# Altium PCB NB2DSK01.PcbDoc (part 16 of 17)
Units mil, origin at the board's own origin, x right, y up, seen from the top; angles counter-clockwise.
Board outline 11815 x 6500.03 mil, 8 copper layers (Top Layer, MidLayer1, MidLayer2, GND, PWR, MidLayer3, MidLayer4, Bottom Layer), stack 74.62 mil thick; 798 components, 1002 nets, 3927 pads, 3182 vias.
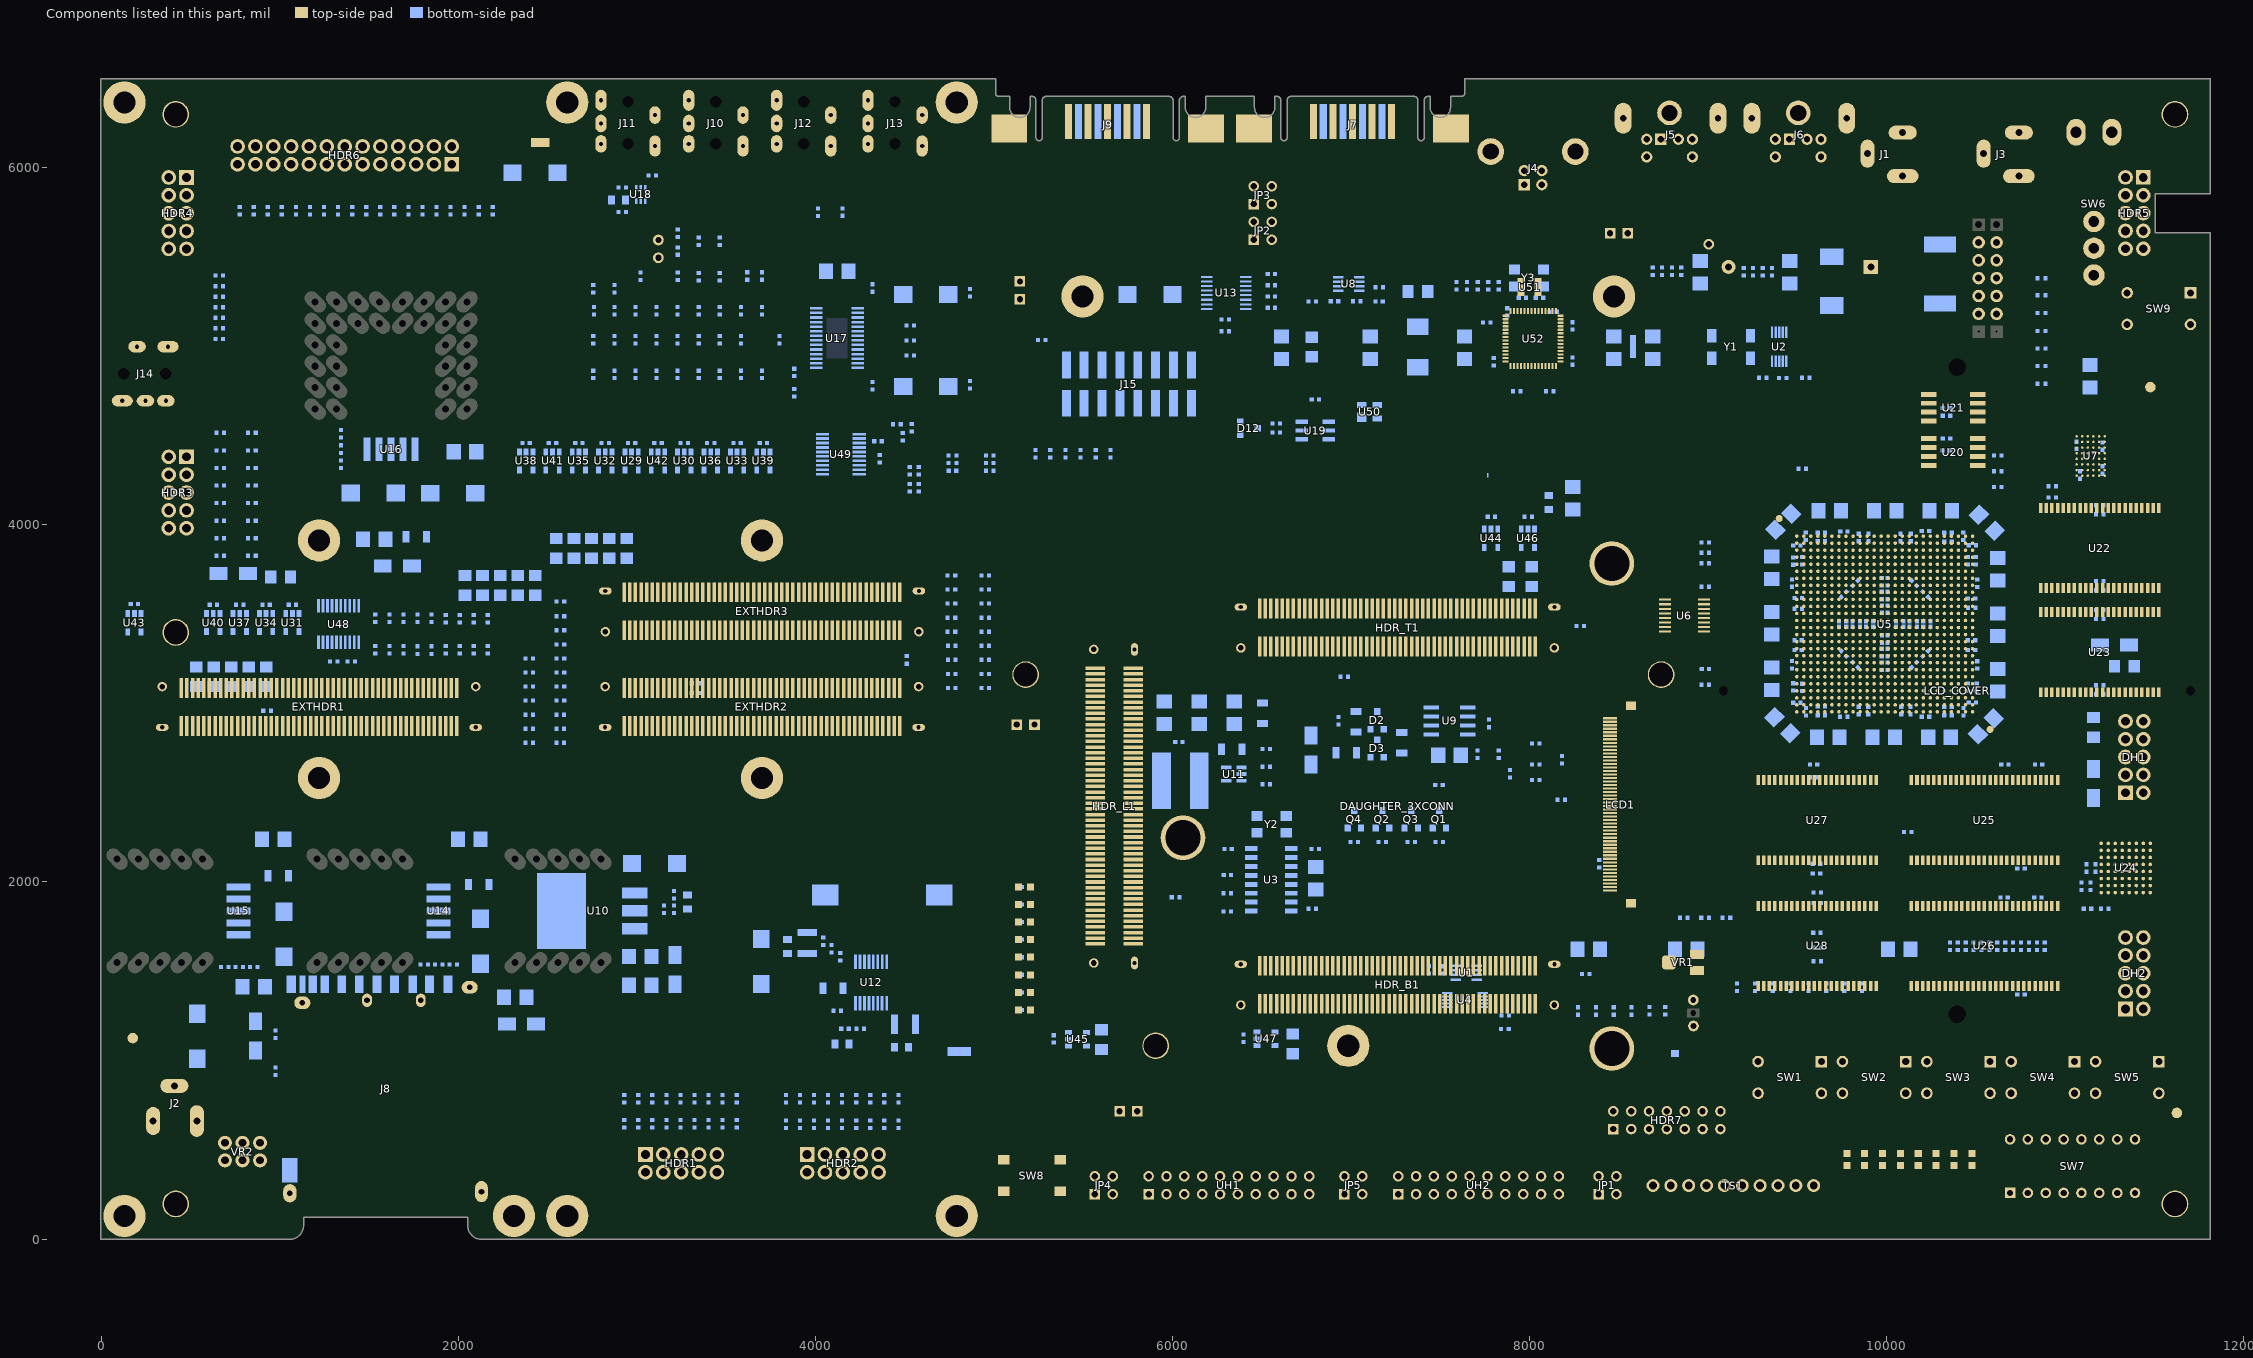
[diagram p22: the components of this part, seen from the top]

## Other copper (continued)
MidLayer3:
  region: 8912,4978.5 8912,4925.5 8926,4925.5 8926,4978.5
  rectangle net 1V2: 9204,3297 9401,3519
  rectangle net CSGND: 4303,4235 4344,4287.4
  rectangle net CSGND: 4284,4383 4346,4524
  rectangle net CSGND: 4344,4235 4519,4524
  rectangle net CSGND: 3997,4235 4303,4524
  rectangle net CSGND: 1196,3228 1468,3588
  rectangle net SHIELD: 10091,89 10495,228
  region net GND: 970.8,5426.84 970.8,4556 2281.17,4556 2281.17,5426.84
  rectangle net AUGND: 3966,4688.98 4276.87,4842.65
  rectangle net 1V2: 9295.68,3398.45 9533.68,3492.45
  rectangle net VCCX: 2228,1458 2873.68,2208
  rectangle net GND: 17,1458 643.68,2208
  rectangle net GND: 1118,1458 1763.68,2208
  text "L3" at 8850.5,4934.5 h35
Bottom Layer:
  rectangle net CAN_V+: 6801.84,6233 6886.4,6379
  rectangle: 6911.09,6233 6995.65,6379
  rectangle net CAN#.CAN_H: 7020.34,6233 7104.9,6379
  rectangle net GND: 7129.59,6233 7214.15,6379
  rectangle net RS232#.DCD: 5758.38,6233 5842.94,6379
  rectangle net RS232#.RTS: 5649.13,6233 5733.69,6379
  rectangle net RS232#.CTS: 5539.88,6233 5624.44,6379
  rectangle net RS232#.RI: 5430.63,6233 5515.18,6379
  region net SHIELD: 7647.54,6299.98 7470.54,6299.98 7470.54,6142.98 7647.54,6142.98
  rectangle net SHIELD: 6368.21,6142.98 6545.21,6299.98
  region net SHIELD: 6276.33,6299 6099.33,6299 6099.33,6142 6276.33,6142
  rectangle net SHIELD: 4997,6142 5174,6299
  region net GND: 9326,3967.41 9382.05,4023.46 9349.7,4055.81 9293.65,3999.76
  region net 2V5: 10510.79,4107 10566.84,4050.95 10599.19,4083.3 10543.14,4139.35
  region net GND: 10640.22,3957.08 10597.22,3914.08 10620.75,3890.55 10663.75,3933.55
  region net GND: 10536.02,2746.42 10592.07,2802.47 10561.27,2833.27 10505.22,2777.22
  region net GND: 9465.59,2782.79 9409.54,2838.84 9377.19,2806.49 9433.24,2750.44
  region net 2V5: 9459.76,2957.52 9406.26,3011.01 9353.26,2958.01 9406.75,2904.52
  region net 2V5: 10559.28,3010.75 10505.79,2957.26 10558.79,2904.26 10612.28,2957.75
  region net 2V5: 10523.66,4008.16 10470.16,4061.65 10417.16,4008.64 10470.65,3955.15
  region: 8912,4872.5 8912,4819.5 8926,4819.5 8926,4872.5
  region net 2V5: 9519.55,3937.65 9580.45,3998.55 9519.2,4059.8 9458.3,3998.9
  rectangle net 1V2: 3770,1696.4 3930,1990
  region net VCCX: 7955,2079 7955,2148 7895,2148 7895,2079
  region net VCCX: 7954,2009 7954,2038 7894,2038 7894,2009
  region net DBPOWER.3V3: 7981,1646 7925,1646 7925,1594 7981,1594
  region net VCCX: 7983,1260 7922,1260 7922,1203 7983,1203
  region net DBPOWER.5V0: 8086.8,1369 8048.19,1369 8048.19,1257 8086.8,1257
  rectangle net VCCX: 2248.68,1488.45 2867.85,2188.45
  rectangle net GND: 23.68,1477 642.85,2207.2
  rectangle net 3V3: 9965.68,3422.45 10010.68,3466.45
  rectangle net GND: 4593.68,1038.45 4673.68,1253.45
  rectangle net GND: 3668.68,1283.45 3768.68,1368.45
  rectangle net GND: 3838.68,1488.45 4008.68,1568.45
  rectangle net 5V0: 4303.68,1103.45 4393.68,1258.45
  region net GND: 10569.27,228 10538.64,228 10538.64,89 10569.27,89
  rectangle net GND: 10016.73,89 10047.67,228
  rectangle net SHIELD: 942.68,225 1001,648
  region net SHIELD: 986.68,185.45 986.68,233.45 818.68,233.45 818.68,185.45
  region net SHIELD: 640,648 588,648 588,225 640,225
  rectangle net SHIELD: 588,593 1001,648
  rectangle net SHIELD: 588,225 1001,391.73
  rectangle net SHIELD: 10091,89 10495,228
  rectangle net GND: 8047.06,1459.38 8085.67,1604.37
  region net 9V0: 7617,2952 7484,2952 7484,2849 7617,2849
  rectangle net AUGND: 4054.13,5203.74 4183.07,5231.3
  rectangle net AUGND: 3960.63,4759.84 4279.53,4862.21
  rectangle net AUGND: 4054.13,4861.22 4183.07,4888.78
  rectangle net AUGND: 4054.13,5178.15 4183.07,5205.71
  rectangle net AUGND: 4054.13,5152.56 4183.07,5180.12
  rectangle net AUGND: 4054.13,5126.97 4183.07,5154.53
  rectangle net AUGND: 3960.63,5230.32 4279.53,5330.71
  rectangle net AUGND: 4287.4,4964.57 4358.27,5015.75
  rectangle net AUGND: 3854.33,5000 3943.9,5066.93
  rectangle net GND: 1143.68,1481.88 1762.85,2204.6
  region net GND: 970.8,5428.45 970.8,4549 2236.22,4549 2236.22,5428.45
  rectangle net PBPOWER.1V2PBB: 3310,3149 3336,3186
  region net PBPOWER.1V8PBB: 3272.68,3197.46 3246.68,3197.46 3246.68,3160.46 3272.68,3160.46
  rectangle net PBPOWER.2V5PBB: 3184.02,3149 3210.02,3186
  region net PBPOWER.3V3PBB: 3146.69,3197.46 3120.69,3197.46 3120.69,3160.46 3146.69,3160.46
  rectangle net NetF1_1: 10220,5569.63 10378,5940
  region net 5VUSW: 10237.55,5509 10237.55,5238.92 10360.55,5238.92 10360.55,5509
  region net 5VUSW: 9643,5514.68 9643,5303 9744,5303 9744,5514.68
  region net GND: 9643,5241.06 9643,5099 9744,5099 9744,5241.06
  rectangle net 2V5: 895,1542 1047,1634
  rectangle net NetL2_1: 4318,1376 4599,1502
  rectangle net 1V2: 3770,1866 4132,1990
  region net SHIELD: 10494.85,205.58 10513.68,201.45 10494.85,197.58 10494.85,205.58
  region net 3V3: 10413.39,3334.65 10437.01,3350.39 10448.82,3350.39 10448.82,3303.15 10437.01,3303.15 10413.39,3318.9
  region net 3V3: 10413.39,3570.87 10437.01,3586.62 10448.82,3586.62 10448.82,3539.37 10437.01,3539.37 10413.39,3555.12
  region net 3V3: 10098.43,3870.08 10082.68,3893.7 10082.68,3905.51 10129.92,3905.51 10129.92,3893.7 10114.17,3870.08
  region net 3V3: 9862.2,3870.08 9846.46,3893.7 9846.46,3905.51 9893.7,3905.51 9893.7,3893.7 9877.95,3870.08
  region net 3V3: 9562.99,3555.12 9539.37,3539.37 9527.56,3539.37 9527.56,3586.61 9539.37,3586.61 9562.99,3570.87
  region net 3V3: 9562.99,3318.9 9539.37,3303.15 9527.56,3303.15 9527.56,3350.39 9539.37,3350.39 9562.99,3334.64
  region net 3V3: 9877.95,3019.69 9893.7,2996.06 9893.7,2984.25 9846.46,2984.25 9846.46,2996.06 9862.2,3019.69
  region net 3V3: 10114.18,3019.69 10129.92,2996.06 10129.92,2984.25 10082.68,2984.25 10082.68,2996.06 10098.43,3019.69
  region net GND: 10538.85,205.58 10519.32,201.58 10538.85,197.58 10538.85,205.58
  region net GND: 10538.8,195.58 10519.26,191.58 10538.8,187.58 10538.8,195.58
  region net SHIELD: 10494.8,195.58 10513.68,191.45 10494.8,187.58 10494.8,195.58
  region net GND: 10538.8,185.58 10519.26,181.58 10538.8,177.58 10538.8,185.58
  region net SHIELD: 10494.8,185.58 10513.68,181.45 10494.8,177.58 10494.8,185.58
  region net GND: 10538.8,175.58 10519.68,171.45 10538.8,167.58 10538.8,175.58
  region net SHIELD: 10494.8,175.58 10514.33,171.58 10494.8,167.58 10494.8,175.58
  region net GND: 10538.8,165.58 10519.26,161.58 10538.8,157.58 10538.8,165.58
  region net SHIELD: 10494.8,165.58 10513.68,161.45 10494.8,157.58 10494.8,165.58
  region net GND: 10538.8,155.58 10519.26,151.58 10538.8,147.58 10538.8,155.58
  region net SHIELD: 10494.8,155.58 10513.68,151.45 10494.8,147.58 10494.8,155.58
  region net GND: 10538.8,145.58 10519.68,141.45 10538.8,137.58 10538.8,145.58
  region net SHIELD: 10494.8,145.58 10514.33,141.58 10494.8,137.58 10494.8,145.58
  region net GND: 10538.8,135.58 10519.68,131.45 10538.8,127.58 10538.8,135.58
  region net SHIELD: 10494.8,135.58 10514.33,131.58 10494.8,127.58 10494.8,135.58
  region net GND: 10538.8,125.58 10519.68,121.45 10538.8,117.58 10538.8,125.58
  region net SHIELD: 10494.8,125.58 10514.33,121.58 10494.8,117.58 10494.8,125.58
  region net GND: 10538.8,115.58 10519.68,111.45 10538.8,107.58 10538.8,115.58
  region net SHIELD: 10494.8,115.58 10514.33,111.58 10494.8,107.58 10494.8,115.58
  region net GND: 10047.28,115.58 10066.81,111.58 10047.28,107.58 10047.28,115.58
  region net SHIELD: 10091.28,115.58 10072.68,111.45 10091.28,107.58 10091.28,115.58
  region net GND: 10047.28,125.58 10066.81,121.58 10047.28,117.58 10047.28,125.58
  region net SHIELD: 10091.28,125.58 10072.68,121.45 10091.28,117.58 10091.28,125.58
  region net GND: 10047.28,135.58 10066.81,131.58 10047.28,127.58 10047.28,135.58
  region net SHIELD: 10091.28,135.58 10072.68,131.45 10091.28,127.58 10091.28,135.58
  region net GND: 10047.28,145.58 10066.81,141.58 10047.28,137.58 10047.28,145.58
  region net SHIELD: 10091.28,145.58 10072.68,141.45 10091.28,137.58 10091.28,145.58
  region net GND: 10047.28,155.58 10066.81,151.58 10047.28,147.58 10047.28,155.58
  region net SHIELD: 10091.28,155.58 10072.68,151.45 10091.28,147.58 10091.28,155.58
  region net GND: 10047.15,165.45 10066.68,161.45 10047.15,157.45 10047.15,165.45
  region net SHIELD: 10091.28,165.58 10071.74,161.58 10091.28,157.58 10091.28,165.58
  region net GND: 10047.28,175.58 10066.81,171.58 10047.28,167.58 10047.28,175.58
  region net SHIELD: 10091.28,175.58 10072.68,171.45 10091.28,167.58 10091.28,175.58
  region net GND: 10047.28,185.58 10066.81,181.58 10047.28,177.58 10047.28,185.58
  region net SHIELD: 10091.28,185.58 10072.68,181.45 10091.28,177.58 10091.28,185.58
  region net GND: 10047.28,195.58 10066.81,191.58 10047.28,187.58 10047.28,195.58
  region net SHIELD: 10091.28,195.58 10072.68,191.45 10091.28,187.58 10091.28,195.58
  region net SHIELD: 10091.33,205.58 10072.68,201.45 10091.33,197.58 10091.33,205.58
  region net GND: 10047.33,205.58 10066.87,201.58 10047.33,197.58 10047.33,205.58
  text "BL" at 8850.5,4828.5 h35
GND (plane layer: these items are gaps in the copper):
  circle w60: c5096.6,798.52 r38.29
  region: 8928.5,4817 8928.5,5031.5 8796.5,5031.5 8796.5,4817
  region: 8796.5,5246 8796.5,5084.5 8928.5,5084.5 8928.5,5246
  lines w5: 8811,5057.37 8839.91,5057.37 ; 8811,5057.37 8810.92,5046.77 8839.91,5057.37 ; 8811,5057.37 8810.92,5067.98 8839.91,5057.37
  lines w7: 8814.45,5053.13 8824.35,5053.13 ; 8814.45,5061.62 8824.35,5061.62
  text "P1" at 8850.5,5040.5 h35
  text "GND" at 358.27,425.2 h34
PWR (plane layer: these items are gaps in the copper):
  circle w60: c5096.6,798.52 r38.29
  region: 8796.5,5246 8796.5,5031.5 8928.5,5031.5 8928.5,5246
  region: 8928.5,4817 8928.5,4978.5 8796.5,4978.5 8796.5,4817
  lines w5: 8811,5004.37 8810.92,5014.98 8839.91,5004.37 ; 8811,5004.37 8810.92,4993.77 8839.91,5004.37 ; 8811,5004.37 8839.91,5004.37
  lines w7: 8814.45,5000.13 8824.35,5000.13 ; 8814.45,5008.62 8824.35,5008.62
  lines w38: 10984.46,5474 11280.74,5474
  lines w40: 788,582 925.2,582 4720,582 5047,255 5121,181 9968,181 10042,255 10148,361 10401,361 11040,361 11415,736 11415,1099 11527,1211 11527,4506 11380.53,4652.47 11380.53,5077.94 11280.74,5177.72 11280.74,5331.26 11280.74,5778.26 ; 789,0 789,937.33 789,1143.33 ; 1299.84,3833.31 1394.99,3928.45 1673.68,3928.45 1723.68,3978.45 1723.68,4138.45 1758.68,4173.45 1888.68,4173.45 2510.85,4173.45 2615.9,4068.4 2615.9,3766.4 2528.7,3679.2 2134.9,3679.2 2087.6,3726.5 2087.6,3851.4 2061.6,3877.4 2014.5,3877.4 1983.8,3846.7 1983.8,3685.1 1969.15,3670.45 1815.68,3670.45 1503.68,3670.45 1187.45,3354.23 610.13,3354.23 586.61,3330.71 586.61,1833.45 2505.74,1833.45 3681.34,1833.45 4603.68,1833.45 ; 1303.15,3836.61 1230.32,3763.78 701.71,3763.78 653.54,3811.95 653.54,3876.17 653.54,5673.23 763.78,5783.47 2456.69,5783.47 2503.94,5736.22 2503.94,4685.04 2637.8,4551.18 4663.86,4551.18 5216.6,5103.92 5560.61,5103.92 6000.92,5103.92 6112,5215 6112,5343 6298,5529 8696.54,5529 10929.46,5529 10973.46,5485 10984.46,5474 ; 4605.32,1835.09 4603.68,1833.45 ; 4755.91,3.94 4759.84,0 ; 4912,6496.06 4912,6043 4964,5991 8398,5991 8423.45,6016.45 8622,6215 8961,6215 9015,6161 9286,6161 9338,6213 9680,6213 9720,6173 9737,6156 9822,6156 9881,6215 10844,6215 11280.74,5778.26 ; 9587,5528 9587,5292 11280.74,5292 ; 11280.74,5606 11280.74,5778.26 ; 789,1143.33 925.2,1279.53 ; 789,1143.33 925.2,1279.53 ; 925.2,1279.53 2947.61,1279.53 3134.97,1092.17 4099.18,1092.17 4235.64,955.71 4528.54,955.71 4893.51,955.71 5934.3,1996.5 6165.4,1996.5 6283.3,2114.4 6306.9,2138 6306.9,2714.6 6306.9,2763 6268,2801.9 6219.6,2801.9 5948.4,2801.9 5884.7,2738.2 4979.95,1833.45 4603.68,1833.45
  text "P2" at 8850.5,4987.5 h35
  text "3V3" at 853.68,648.45 h78.74
  text "5V0" at 318.25,475.42 h78.74
  text "SHIELD" at 1018.68,433.45 h78.74
Multi-Layer:
  text "1" at 19394.94,-5240.28 h120
  text "OF" at 19590.02,-5239.73 h80
  text "1" at 19829.94,-5240.28 h120

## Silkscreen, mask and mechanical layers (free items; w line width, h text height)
Top Overlay:
  drawing of 8418 lines, arcs and shapes, not listed
  text "KMDGX-6S-BS2715C" at 8539,6412 h34
  text "KMDGX-6S-BS3395C" at 9259.47,6412 h34
  text "5VDC" at 10324.54,6411.05 h80
  text "POWER" at 10285.17,6337.59 h80
  text "PC PARALLEL PORT" at 911,6272 h102.36
  text "IN" at 10387.53,6264.31 h80
  text "DC" at 10285,6113 h70
  text "L" at 2862,6073 h34
  text "R" at 3020,6073 h34
  text "L" at 3354.13,6073 h34
  text "R" at 3512.13,6073 h34
  text "L" at 3846.25,6073 h34
  text "R" at 4004.25,6073 h34
  text "L" at 4358.06,6073 h34
  text "R" at 4516.06,6073 h34
  text "NANOTALK" at 57,6030 h90
  text "NANOTALK" at 11332.23,6030.39 h90
  text "MICROPHONE" at 2773.76,5994.71 h60
  text "LINE OUT" at 3809.19,5995.5 h60
  text "LINE IN" at 3347.03,5993.92 h60
  text "HEADPHONES" at 4261.5,5992.35 h60
  text "MOUSE" at 9389,5907 h80
  text "KEYBOARD" at 8568,5903 h80
  text "1+2  CiA DS102" at 6678,5869.37 h60
  text "PIN 2 - RXD" at 5179.8,5861.6 h60
  text "TOP SIDE" at 1238.22,5842.53 h100
  text "PIN 3 - TXD" at 5179.8,5803.36 h60
  text "2+4 and 1+3  NB1" at 6677.94,5796.32 h60
  text "INSERT" at 76.24,5785.88 h40
  text "RS232" at 5626.7,5776 h120
  text "CAN" at 7291.58,5775.5 h120
  text "PIN 7 - RTS" at 5179.8,5744.56 h60
  text "KEY" at 115.18,5722.49 h40
  text "PIN 8 - CTS" at 5179.8,5685.68 h60
  text "2" at 6348.68,5678.45 h39.37
  text "4" at 6618.68,5678.45 h39.37
  text "1+2 CAN 1Mbps Mode" at 6678,5672.54 h55
  text "0V" at 10388,5670 h45
  text "0V" at 10694,5668 h45
  text "GND" at 10791,5660 h70.87
  text "DOWN" at 89.85,5659.1 h40
  text "GND" at 10205,5659 h70.87
  text "USB 2.0" at 7854.33,5649.61 h102.36
  text "DS102" at 7256.7,5646 h110
  text "EIA-574" at 5611.7,5645.4 h110
  text "PINS 1+4+6" at 5179.8,5626.8 h60
  text "3+4 CAN 120R  TERM" at 6678,5593.55 h55
  text "-7V5" at 10210,5559 h70.87
  text "FROM" at 32,5553 h70
  text "TO" at 11529.26,5553.39 h70
  text "GND" at 8425.68,5516.45 h78.74
  text "MASTER" at 30,5489 h70
  text "SLAVE" at 11527.26,5489.39 h70
  text "16V5" at 10198,5459 h70.87
  text "+" at 9001.81,5444.99 h40
  text "LM4849MH" at 3957.34,5381.65 h70
  text "9V0" at 10230,5359 h70.87
  text "CR2032" at 8775.5,5329.64 h80
  text "GND" at 4900,5270 h78.74
  text "3V0" at 9083.8,5234.8 h60
  text "DAUGHTER BOARD" at 6443,5199 h102.36
  text "VBAT" at 10791,5159 h70.87
  text "AUDIO TEST" at 37.82,5079.05 h86.61
  text "POWER SUPPLY TEST POINTS" at 10314,5045 h50
  text "TP0" at 10152,5038 h80
  text "R" at 423.06,4916.3 h34 r90
  text "GROUND" at 1442.68,4888.45 h94.49
  text "L" at 423.06,4758.3 h34 r90
  text "25P80" at 10358,4735 h36 r270
  text "AUDIO AMPLIFIER" at 3922.66,4672.45 h50
  text "XCF08PFS48C" at 10989,4615 h35
  text "SYSTEM 3V3 SUPPLY" at 1384,4518 h52
  text "25P80" at 10358,4486.97 h36 r270
  text "SYSTEM JTAG" at 15.76,4451.81 h80
  text "NB2DSK01.08" at 5883.26,4442.23 h98.43
  text "Desktop" at 5883.26,4384.24 h60
  text "NanoBoard" at 5883.27,4308.27 h60
  text "NB2DSK01.08" at 6536.61,4272.23 h60
  text "FLASH" at 11061.02,4149.33 h34
  text "PERIPHERAL BOARD C" at 3185,4106 h102.36
  text "XC3S1500-4FG676C" at 9512.3,4019.48 h50
  text "SRAM-256Kx16" at 10932.32,3907.25 h50
  text "AD7843" at 8863,3561 h30 r270
  text "SRAM-256Kx16" at 10932.32,3324.57 h50
  text "SRAM" at 11085.19,2950.27 h60
  text "USER POWER CONFIG" at 7117.98,2823 h34
  text "JP4/JP5" at 6880.65,2819 h60
  text "GND" at 5096,2760 h78.74
  text "SDRAM" at 10413.03,2680.78 h60
  text "SRAM" at 9501.7,2679.2 h60
  text "5V0" at 7086.18,2651.75 h75
  text "3V3" at 7460.63,2651.69 h75
  text "- POWER CONFIG USER I/O PORT A" at 6905.44,2490.39 h32
  text "DEBUG PORT A" at 11561,2489 h40 r90
  text "JP4" at 6782.44,2486.69 h60
  text "- POWER CONFIG USER I/O PORT B" at 6905.44,2427.39 h32
  text "JP5" at 6782.44,2423.69 h60
  text "PERIPHERAL BOARD A" at 708,2325 h102.36
  text "PERIPHERAL BOARD B" at 3188.32,2324 h102.36
  text "SRAM-256Kx16" at 9333.07,2251.71 h50
  text "DRAM-16Mx16" at 10299.55,2250.13 h50
  text "DAC REFERENCE CONFIG" at 7015.3,2168.15 h34
  text "JP1" at 6880.33,2164.15 h60
  text "HOST STATUS" at 4912,2053 h60
  text "2.048" at 7085.92,1996.84 h75
  text "3.30" at 7460.31,1996.9 h75
  text "SL1" at 4969.82,1949.12 h70.87
  text "SL2" at 4969.82,1851.45 h70.87
  text "GROUND" at 1293.68,1828.45 h94.49
  text "GROUND" at 148.68,1818.45 h94.49
  text "VCCX" at 2443.68,1818.45 h94.49
  text "S29GL256N11FFIV" at 11128.8,1763 h35
  text "SL3" at 4969.82,1753.45 h70.87
  text "FLASH" at 11131.2,1705.2 h34
  text "CONTRAST" at 8739,1700 h34
  text "SL4" at 4969.82,1654.45 h70.87
  text "SL5" at 4969.82,1555.45 h70.87
  text "SRAM-256Kx16" at 9333.07,1546.99 h50
  text "DRAM-16Mx16" at 10299.55,1545.41 h50
  text "SL6" at 4969.82,1457.45 h70.87
  text "DAUGHTER BD ADJ SUPPLY" at 2246,1424 h52
  text "SYSTEM 2V5 SUPPLY" at 73,1422 h52
  text "SYSTEM 1V8 SUPPLY" at 1218,1422 h52
  text "SL7" at 4969.82,1358.45 h70.87
  text "DEBUG PORT B" at 11561,1277.98 h40 r90
  text "SL8" at 4969.82,1260.45 h70.87
  text "K" at 5226.74,1093.3 h30
  text "TOUCH" at 8684.02,972.01 h100
  text "5VDC OUT" at 165.35,964.57 h80
  text "SCREEN" at 8685.98,890 h100
  text "V8" at 8050,674 h140
  text "DC" at 726.89,656.96 h80
  text "GND" at 5675,596 h78.74
  text "USER LEDS" at 9988,569 h55
  text "K" at 10549,556 h30
  text "USER BOARD POWER" at 110.24,460.63 h50
  text "I2C - DAC - ADC" at 8704.73,448.82 h102.36
  text "CONFIG SWITCH 7" at 10734.16,384.61 h50
  text "2" at 5473.68,333.45 h39.37
  text "4" at 5728.68,333.45 h39.37
  text "2" at 6873.68,333.45 h39.37
  text "4" at 7128.68,333.45 h39.37
  text "2" at 8293.68,333.45 h39.37
  text "4" at 8548.68,333.45 h39.37
  text "7" at 9757.78,284.37 h94.49
  text "6" at 9857.78,284.37 h94.49
  text "5" at 9957.78,284.37 h94.49
  text "4" at 10057.78,284.37 h94.49
  text "3" at 10156.2,284.37 h94.49
  text "2" at 10254.63,284.37 h94.49
  text "1" at 10357.78,284.37 h94.49
  text "0" at 10457.78,284.37 h94.49
  text "3" at 7128.68,233.45 h39.37
  text "1" at 8303.68,233.45 h39.37
  text "3" at 8548.68,233.45 h39.37
  text "1" at 5483.68,228.45 h39.37
  text "3" at 5728.68,228.45 h39.37
  text "1" at 6883.68,228.45 h39.37
  text "ESD" at 9952,186 h60
  text "SD/Multimedia Card" at 1191.68,166.45 h94.49
  text "User Board A" at 2982.68,164.45 h94.49
  text "User Board B" at 3882.68,164.45 h94.49
  text "DAUGHTER BD" at 4998.28,129.63 h65
  text "+" at 8673.11,118.59 h40
  text "-" at 9573.11,118.59 h40
  text "1" at 9280,117 h66.93
  text "0" at 9177,116 h66.93
  text "2" at 9376,116 h66.93
  text "0" at 8776,115 h66.93
  text "1" at 8882,115 h66.93
  text "2" at 8977,115 h66.93
  text "3" at 9080,115 h66.93
  text "3R" at 9462,115 h66.93
  text "5V" at 5588.68,63.45 h70.87 r90
  text "5V" at 6988.68,63.45 h70.87 r90
  text "3V3" at 7088.68,48.45 h70.87 r90
  text "3V3" at 8508.68,48.45 h70.87 r90
  text "REF" at 8408.68,43.45 h70.87 r90
  text "3V3" at 5688.68,38.45 h70.87 r90
  text "Analogue In" at 9306,36 h65
  text "Analogue Out" at 8741,35 h65
  text "TEST/RESET" at 4993.16,32.7 h80
  text "Volume" at 743.68,28.45 h94.49
  text "User Header A" at 6225,24 h94.49
  text "User Header B" at 7626,24 h94.49
  text "TOUCH HERE FIRST" at 9751,20 h34
Bottom Overlay:
  drawing of 3399 lines, arcs and shapes, not listed
  text "1" at 2862.06,6417.43 h35
  text "PURPLE" at 8963.68,6398.45 h100
  text "GREEN" at 9663.68,6398.45 h100
  text "ON/OFF" at 11323.68,6398.45 h100
  text "DC OUT" at 10258.68,6393.45 h100
  text "DC IN" at 10848.68,6393.45 h100
  text "1" at 3354.18,6358.73 h35
  text "1" at 3846.31,6358.73 h35
  text "1" at 4358.12,6358.73 h35
  text "10" at 3056.33,6279.5 h35
  text "10" at 3548.46,6279.5 h35
  text "10" at 4040.59,6279.5 h35
  text "10" at 4552.4,6279.5 h35
  text "11" at 2884.08,6222.85 h35
  text "11" at 3376.2,6222.85 h35
  text "11" at 3868.33,6222.85 h35
  text "11" at 4380.14,6222.85 h35
  text "2" at 8909.88,6203.09 h40
  text "2" at 9630.35,6203.09 h40
  text "2" at 9960.44,6180.1 h40
  text "2" at 10610.84,6180.1 h40
  text "9" at 6791.26,6162.63 h34
  text "6" at 7236.36,6160.71 h34
  text "USB PORT" at 8130,6151.04 h35
  text "4" at 9016.28,6142.7 h40
  text "4" at 9736.75,6142.7 h40
  text "3" at 8571.8,6140.98 h40
  text "3" at 9292.28,6140.98 h40
  text "+" at 6826.31,6125.76 h40 r270
  text "3" at 2873.21,6115.15 h35
  text "3" at 3365.33,6115.15 h35
  text "3" at 3857.46,6115.15 h35
  text "3" at 4369.27,6115.15 h35
  text "2" at 3050.46,6109.29 h35
  text "2" at 3542.59,6109.29 h35
  text "2" at 4034.72,6109.29 h35
  text "2" at 4546.53,6109.29 h35
  text "4" at 7981.56,6061.99 h40
  text "3" at 8079.55,6061.99 h40
  text "3" at 9999.73,6061.99 h40
  text "3" at 10650.13,6061.99 h40
  text "6" at 9016.28,6044.27 h40
  text "6" at 9736.75,6044.27 h40
  text "5" at 8571.8,6042.56 h40
  text "5" at 9292.28,6042.56 h40
  text "RS232 SERIAL PORT" at 5863.3,6016.6 h35
  text "CAN PORT" at 7130.2,6015.9 h35
  text "+" at 10207.73,5970 h40 r180
  text "+" at 10858.12,5970 h40 r180
  text "PINK" at 2893,5940 h60
  text "BLACK" at 3447,5940 h60
  text "GREEN" at 3940,5940 h60
  text "BLUE" at 4404.4,5940.31 h60
  text "PS2 KEYBOARD INTERFACE" at 9100,5940.47 h35
  text "NANOTALK" at 11222,5938 h35
  text "1" at 9960.45,5936.01 h40
  text "1" at 10610.84,5936.01 h40
  text "PS2 MOUSE INTERFACE" at 9785,5935.47 h35
  text "OUT" at 11223,5883 h35
  text "MIC IN" at 3221,5878 h35
  text "LINE IN" at 3625,5878 h35
  text "LINE OUT" at 4119,5878 h35
  text "HEADPHONES" at 4605,5878 h35
  text "BOTTOM SIDE" at 1600,5843 h100
  text "9812" at 3059,5840 h24
  text "1" at 7977.76,5789.04 h40
  text "2" at 8086.75,5789.04 h40
  text "1" at 11276.84,5682.38 h40
  text "+" at 9098.91,5579.96 h40 r270
  text "24MHz" at 8067,5482 h34
  text "3051" at 6993.01,5383.72 h23 r90
  text "3" at 11288.58,5382.38 h40
  text "SYSTEM 3V3 SUPPLY" at 1873,5354 h52.01
  text "3232" at 6310.89,5345.6 h34 r90
  text "FUSE" at 10276,5331 h80 r270
  text "NANOTALK IN" at 525,5279 h35
  text "32K768Hz" at 9240.3,5127.3 h34
  text "AUDIO TEST IN" at 437,5070 h35
  text "3V3" at 5418.57,5009.51 h60
  text "1W" at 5517,5009.19 h60
  text "CS2" at 5644.17,5009.28 h60
  text "CK2" at 5769.85,5009.41 h60
  text "L+" at 5850.33,5009.41 h60
  text "5V" at 5947.7,5009.58 h60
  text "R-" at 6027.37,5009.26 h60
  text "AGND" at 6209,5009.24 h60
  text "1391" at 9447.6,4976.11 h34
  text "2" at 388.69,4919.56 h35
  text "10" at 223.76,4916.63 h35
  text "BLACK" at 696.85,4755.91 h60
  text "1" at 128.09,4743.48 h35
  text "11" at 268.96,4742.3 h35
  text "3" at 374.02,4741.72 h35
  text "DS2406" at 6799.39,4599.65 h28 r90
  text "L-" at 5824.66,4533.69 h60
  text "CK1" at 5418.76,4533.52 h60
  text "DI1" at 5517,4533.46 h60
  text "CS1" at 5635.3,4533.56 h60
  text "DI2" at 5739.78,4533.46 h60
  text "GND" at 5963.66,4533.52 h60
  text "R+" at 6054.66,4533.54 h60
  text "VOL" at 6183.66,4533.52 h60
  text "TO NB2DSK-SPK01" at 6264.1,4382.09 h35
  text "4372" at 2433.42,4345.45 h32
  text "4372" at 2581.06,4345.45 h32
  text "4372" at 2728.69,4345.45 h32
  text "4372" at 2876.33,4345.45 h32
  text "4372" at 3023.97,4345.45 h32
  text "4372" at 3171.61,4345.45 h32
  text "4372" at 3319.24,4345.45 h32
  text "4372" at 3466.88,4345.45 h32
  text "4372" at 3614.52,4345.45 h32
  text "4372" at 3762.16,4345.45 h32
  text "MAX1229" at 4135,4301 h34 r270
  text ".Application_BuildNumber" at 6530.13,4050 h95
  text "BUILD No:" at 6907.79,4050 h50
  text "SVN 6145" at 6530.13,3941.67 h95
  text "REVISION No:" at 7017.76,3941.67 h50
  text "4372" at 7836.96,3912.38 h32
  text "4372" at 8043.65,3912.38 h32
  text "+5V" at 386,3846 h50 r270
  text "MACHINE ID:" at 6988.96,3833.33 h50
  text "GND" at 460,3830 h50 r270
  text ".ComputerName" at 6530.13,3829.39 h95
  text "PCB MANUFACTURER:" at 7324.13,3725 h50
  text "HOST PROGRAMMING" at 557.6,3700.5 h35
  text "PORT" at 557.6,3645.6 h35
  text "4372" at 681.45,3439.94 h32
  text "4372" at 829.09,3439.94 h32
  text "4372" at 976.72,3439.94 h32
  text "4372" at 1124.36,3439.94 h32
  text "4372" at 239.5,3438.9 h32
  text "MAX1229" at 1438,3422 h34
  text "NB2DSK01" at 4077.14,3325.35 h150
  text "GND" at 11355,3053 h50 r90
  text "+5V" at 11429,3037 h50 r90
  text "LM317" at 7526,2825 h34 r270
  text "COMPLIANCE:" at 5169.08,2700.05 h45
  text "CLASS 2" at 4419.08,2610.05 h40
  text "IPC-A-600H" at 5079.08,2610.05 h40
  text "CLASS 2" at 4419.08,2530.05 h40
  text "TYPE 3" at 4669.08,2530.05 h40
  text "IPC-6012D" at 5079.08,2530.05 h40
  text "MANUFACTURE" at 3261.27,2468.01 h40
  text "20MHz" at 6625,2426 h34
  text "DATE" at 3262.37,2401.21 h40
  text "SYSTEM 1.2V SUPPLY" at 4807.09,2283.47 h52.01
  text "DEBUG HEADER A" at 11781,2244 h35
  text "SYSTEM 2V5 SUPPLY" at 541.9,2223.8 h52.01
  text "VCCX SUPPLY" at 2599.3,2223.8 h52.01
  text "SYSTEM 1V8 SUPPLY" at 1648.1,2222.6 h52.01
  text "DESIGNED IN SYDNEY" at 9141,2209 h40
  text "AUSTRALIA" at 9035.43,2120 h50
  text "INDUCTOR" at 4509.28,2010.8 h40
  text "ICS307-02" at 6531,1880 h34 r270
  text "GND" at 11350,1842 h50 r90
  text "+5V" at 11425,1827 h50 r90
  text "2R2/2.2uH" at 4500.28,1817.8 h35
  text "9A 6.8mR" at 4494.28,1757.8 h35
  text "1037" at 7630.02,1456.19 h22 r270
  text "1831" at 4361,1426 h40
  text "5841" at 7633.05,1293.82 h32 r270
  text "4372" at 6537,1176 h32 r90
  text "4372" at 5481.41,1172.98 h32 r90
  text "DEBUG HEADER B" at 11781,1040 h35
  text "5V OUT" at 290,880 h80
  text "SD CARD" at 2382.4,863.2 h35
  text "SD CARD" at 1849.15,810.11 h120
  text "+" at 608.25,808.64 h40 r90
  text "3" at 425,745 h40
  text "VOLUME" at 877.77,694.41 h34
  text "2" at 396,644 h40
  text "1" at 454,643 h40
  text "HIROSE" at 1766.48,629.01 h70
  text "HRS6090003-5" at 1927.89,514.84 h60
  text "USER BD JTAG A" at 2835,500 h35
  text "USER BD JTAG B" at 4949,498 h35
  text "ADC/DAC INPUT/OUTPUT" at 9001,483.9 h28
  text "A" at 5681,169 h50
  text "B" at 7077,169 h50
  text "SPARK GAP" at 10419.49,141.87 h50
  text "USER DIP SWITCH" at 11247.7,121.3 h35
  text "3/5V" at 5656.36,119.7 h25
  text "3/5V" at 7054,119.7 h25
  text "REF" at 8464.32,119.73 h25
  text "ADC/DAC INPUT/OUTPUT" at 9429.6,116.4 h35
  text "USER HEADER B" at 7915.5,115.2 h35
  text "USER HEADER A" at 6513.8,112.7 h35
Top Solder:
  rectangle: 11360.79,104.81 11419.45,179.44
  rectangle: 11260.79,104.81 11319.45,179.44
  rectangle: 11160.79,104.81 11219.45,179.44
  rectangle: 11060.79,104.81 11119.45,179.44
  rectangle: 10960.79,104.81 11019.45,179.44
  rectangle: 10860.79,104.81 10919.45,179.44
  rectangle: 10760.79,104.81 10819.45,179.44
  rectangle: 10660.79,104.81 10719.45,179.44
  region: 7673.78,6388 7569.78,6388 7569.78,6140 7673.78,6140
  rectangle: 6342.21,6140 6446.21,6388
  region: 6302.57,6388 6198.57,6388 6198.57,6140 6302.57,6140
  rectangle: 4971,6140 5075,6388
  rectangle: 8795.4,4815.6 8930,5246.3
  region: 1138.68,5308.45 1138.68,4588.45 2108.68,4588.45 2108.68,5308.45
  rectangle: 10091,89 10495,228
  rectangle: 1143.68,1488.45 1763.68,2188.45
  rectangle: 23.68,1488.45 643.68,2188.45
  rectangle: 2248.68,1488.45 2868.68,2188.45
  rectangle: 3952,4756 4287,5339
  rectangle: 4971.24,6106.8 5246.98,6145.1
  rectangle: 5383.8,6245.3 5452.76,6373.1
  rectangle: 5493.05,6245.3 5562.01,6373.1
  rectangle: 5602.3,6245.3 5671.26,6373.1
  rectangle: 5711.56,6245.3 5780.51,6373.1
  rectangle: 5820.81,6245.3 5889.76,6373.1
  rectangle: 6755.01,6245.3 6823.97,6373.1
  rectangle: 6864.27,6245.3 6933.22,6373.1
  rectangle: 6973.52,6245.3 7042.47,6373.1
  rectangle: 7082.77,6245.3 7151.72,6373.1
  rectangle: 7192.02,6245.3 7260.98,6373.1
  region: 6302.33,6145.1 6026.59,6145.1 6026.59,6106.8 6302.33,6106.8
  rectangle: 6342.45,6106.8 6618.19,6145.1
  region: 7673.54,6145.1 7397.8,6145.1 7397.8,6106.8 7673.54,6106.8
  region: 11807.09,307.09 11807.09,1011.81 11732.28,937.01 11732.28,381.89
  region: 11809.8,2831.25 11809.8,2126.52 11735,2201.33 11735,2756.45
  region: 11809.8,4335.2 11809.8,3630.47 11735,3705.28 11735,4260.39
  region: 2527.56,6496.06 1822.84,6496.06 1897.64,6421.26 2452.76,6421.26
  lines w4: 10660.17,113.53 ccw(c10675.14,113.53) 10675.14,98.55 10705.22,98.55 ccw(c10705.22,113.53) 10720.19,113.53 10720.19,170.64 ccw(c10705.22,170.64) 10705.22,185.61 10675.14,185.61 ccw(c10675.14,170.64) 10660.17,170.64 10660.17,113.53 ; 10760.17,113.53 ccw(c10775.14,113.53) 10775.14,98.55 10805.22,98.55 ccw(c10805.22,113.53) 10820.19,113.53 10820.19,170.64 ccw(c10805.22,170.64) 10805.22,185.61 10775.14,185.61 ccw(c10775.14,170.64) 10760.17,170.64 10760.17,113.53 ; 10860.17,113.53 ccw(c10875.14,113.53) 10875.14,98.55 10905.22,98.55 ccw(c10905.22,113.53) 10920.19,113.53 10920.19,170.64 ccw(c10905.22,170.64) 10905.22,185.61 10875.14,185.61 ccw(c10875.14,170.64) 10860.17,170.64 10860.17,113.53 ; 10960.17,113.53 ccw(c10975.14,113.53) 10975.14,98.55 11005.22,98.55 ccw(c11005.22,113.53) 11020.19,113.53 11020.19,170.64 ccw(c11005.22,170.64) 11005.22,185.61 10975.14,185.61 ccw(c10975.14,170.64) 10960.17,170.64 10960.17,113.53 ; 11060.17,113.53 ccw(c11075.14,113.53) 11075.14,98.55 11105.22,98.55 ccw(c11105.22,113.53) 11120.19,113.53 11120.19,170.64 ccw(c11105.22,170.64) 11105.22,185.61 11075.14,185.61 ccw(c11075.14,170.64) 11060.17,170.64 11060.17,113.53 ; 11160.17,113.53 ccw(c11175.14,113.53) 11175.14,98.55 11205.22,98.55 ccw(c11205.22,113.53) 11220.19,113.53 11220.19,170.64 ccw(c11205.22,170.64) 11205.22,185.61 11175.14,185.61 ccw(c11175.14,170.64) 11160.17,170.64 11160.17,113.53 ; 11260.17,113.53 ccw(c11275.14,113.53) 11275.14,98.55 11305.22,98.55 ccw(c11305.22,113.53) 11320.19,113.53 11320.19,170.64 ccw(c11305.22,170.64) 11305.22,185.61 11275.14,185.61 ccw(c11275.14,170.64) 11260.17,170.64 11260.17,113.53 ; 11360.17,113.53 ccw(c11375.14,113.53) 11375.14,98.55 11405.22,98.55 ccw(c11405.22,113.53) 11420.19,113.53 11420.19,170.64 ccw(c11405.22,170.64) 11405.22,185.61 11375.14,185.61 ccw(c11375.14,170.64) 11360.17,170.64 11360.17,113.53
  lines w8: 10667.69,103.04 10712.64,103.04 ; 10667.69,181.12 10712.64,181.12 ; 10767.69,103.04 10812.64,103.04 ; 10767.69,181.12 10812.64,181.12 ; 10867.69,103.04 10912.64,103.04 ; 10867.69,181.12 10912.64,181.12 ; 10967.69,103.04 11012.64,103.04 ; 10967.69,181.12 11012.64,181.12 ; 11067.69,103.04 11112.64,103.04 ; 11067.69,181.12 11112.64,181.12 ; 11167.69,103.04 11212.64,103.04 ; 11167.69,181.12 11212.64,181.12 ; 11267.69,103.04 11312.64,103.04 ; 11267.69,181.12 11312.64,181.12 ; 11367.69,103.04 11412.64,103.04 ; 11367.69,181.12 11412.64,181.12
Bottom Solder:
  drawing of 79 lines, arcs and shapes, not listed
1. Boundary:
  lines w3.94: 1477.7,6496.06 0,6496.06 ; 7558.86,6397.64 7618.11,6397.64 ccw(c7618.11,6417.32) 7637.8,6417.32 7637.8,6496.06 11811.03,6496.06 11811.02,5856.42 11501.2,5856.42 11501.2,5634.92 11811.02,5634.92 11811.02,0 2132.42,0 cw(c2132.42,78.74) 2053.68,78.74 2053.68,123.45 1132.13,123.45 1132.13,78.74 cw(c1053.39,78.74) 1053.39,0 0,0 0,6496.06 ; 7558.87,6397.64 7558.87,6338.58 cw(c7499.82,6338.58) 7440.76,6338.58 7440.76,6397.64 7431.12,6397.64 ccw(c7431.12,6377.95) 7411.43,6377.95 7411.43,6169.29 cw(c7391.75,6169.29) 7372.06,6169.29 7372.06,6377.95 ccw(c7352.38,6377.95) 7352.38,6397.64 6663.4,6397.64 ccw(c6663.4,6377.95) 6643.72,6377.95 6643.72,6169.29 cw(c6624.03,6169.29) 6604.35,6169.29 6604.35,6377.95 ccw(c6584.66,6377.95) 6584.66,6397.64 6575.02,6397.64 6575.02,6338.58 cw(c6515.96,6338.58) 6456.91,6338.58 6456.91,6397.64 6187.66,6397.64 6187.66,6338.58 cw(c6128.61,6338.58) 6069.55,6338.58 6069.55,6397.64 6059.91,6397.64 ccw(c6059.91,6377.95) 6040.22,6377.95 6040.22,6169.29 cw(c6020.54,6169.29) 6000.85,6169.29 6000.85,6377.95 ccw(c5981.16,6377.95) 5981.16,6397.64 5292.19,6397.64 ccw(c5292.19,6377.95) 5272.5,6377.95 5272.5,6169.29 cw(c5252.82,6169.29) 5233.13,6169.29 5233.13,6377.95 ccw(c5213.45,6377.95) 5213.45,6397.64 5203.8,6397.64 5203.8,6338.58 cw(c5144.75,6338.58) 5085.69,6338.58 5085.69,6397.64 5026.43,6397.64 cw(c5026.43,6417.32) 5006.74,6417.32 5006.74,6496.06 0,6496.06
2. Plated Through Routes:
  lines w0.39: 4977.22,6169.29 5528.4,6169.29 ; 4980.32,6169.29 5167.33,6169.29 ; 5252.81,5824.8 5252.81,6011.81 ; 5252.81,5893.7 5252.81,6444.88 ; 5252.81,6326.77 5252.81,6513.78 ; 5636.67,5390.68 5636.67,7244.31 ; 5744.93,6169.29 6296.11,6169.29 ; 6020.52,5824.8 6020.52,6011.81 ; 6020.52,5893.7 6020.52,6444.88 ; 6020.52,6326.77 6020.52,6513.78 ; 6250,6169.29 6437.01,6169.29 ; 6279.53,6169.29 6466.54,6169.29 ; 6348.43,6169.29 6899.61,6169.29 ; 6624.02,5824.8 6624.02,6011.81 ; 6624.02,5893.7 6624.02,6444.88 ; 6624.02,6326.77 6624.02,6513.78 ; 6781.5,6169.29 6968.51,6169.29 ; 7007.88,5391.66 7007.88,7245.29 ; 7047.25,6169.29 7234.26,6169.29 ; 7116.15,6169.29 7667.33,6169.29 ; 7391.74,5824.8 7391.74,6011.81 ; 7391.74,5893.7 7391.74,6444.88 ; 7391.74,6326.77 7391.74,6513.78 ; 7549.22,6169.29 7736.22,6169.29 ; 0,0 11811.03,0 11811.03,6496.06 7637.8,6496.06 7637.8,6417.32 cw(c7618.11,6417.32) 7618.11,6397.64 7558.86,6397.64 7558.86,6338.58 cw(c7499.81,6338.58) 7440.75,6338.58 7440.75,6397.64 7431.11,6397.64 ccw(c7431.11,6377.95) 7411.42,6377.95 7411.42,6169.29 cw(c7391.74,6169.29) 7372.05,6169.29 7372.05,6377.95 ccw(c7352.37,6377.95) 7352.37,6397.64 6663.39,6397.64 ccw(c6663.39,6377.95) 6643.7,6377.95 6643.7,6169.29 cw(c6624.02,6169.29) 6604.33,6169.29 6604.33,6377.95 ccw(c6584.65,6377.95) 6584.65,6397.64 6575,6397.64 6575,6338.58 cw(c6515.95,6338.58) 6456.89,6338.58 6456.89,6397.64 6187.65,6397.64 6187.65,6338.58 cw(c6128.59,6338.58) 6069.54,6338.58 6069.54,6397.64 6059.89,6397.64 ccw(c6059.89,6377.95) 6040.21,6377.95 6040.21,6169.29 cw(c6020.52,6169.29) 6000.84,6169.29 6000.84,6377.95 ccw(c5981.15,6377.95) 5981.15,6397.64 5292.18,6397.64 ccw(c5292.18,6377.95) 5272.49,6377.95 5272.49,6169.29 cw(c5252.81,6169.29) 5233.12,6169.29 5233.12,6377.95 ccw(c5213.44,6377.95) 5213.44,6397.64 5203.79,6397.64 5203.79,6338.58 cw(c5144.74,6338.58) 5085.68,6338.58 5085.68,6397.64 5026.43,6397.64 cw(c5026.43,6417.32) 5006.74,6417.32 5006.74,6496.06 0,6496.06 0,0 ; 5016.59,6161.42 5016.59,6279.53 5154.38,6279.53 5154.38,6161.42 5016.59,6161.42 ; 6118.95,6161.42 6256.74,6161.42 6256.74,6279.53 6118.95,6279.53 6118.95,6161.42 ; 6387.8,6161.42 6525.59,6161.42 6525.59,6279.53 6387.8,6279.53 6387.8,6161.42 ; 7490.16,6161.42 7627.96,6161.42 7627.96,6279.53 7490.16,6279.53 7490.16,6161.42
5. Daughter:
  circle w5: c11700.79,3070.86 r25.59
  circle w5: c10393.7,4881.89 r49.21
  circle w5: c10393.7,1259.84 r49.21
  circle w5: c8736.22,3161.42 r68.9
  circle w5: c11614.17,196.85 r68.9
  circle w5: c11614.17,6299.21 r68.9
  circle w5: c9086.61,3070.86 r25.59
  lines w5: 9064.96,1903.26 9036.29,1903.26 9036.29,1209.77 ccw(c9055.95,1209.76) 9054.27,1190.18 ccw(c10393.7,16781.5) 11733.13,1190.18 ccw(c11731.45,1209.76) 11751.11,1209.77 11751.11,4931.96 ccw(c11731.45,4931.97) 11733.13,4951.55 ccw(c10393.7,-10639.77) 9054.27,4951.55 ccw(c9055.95,4931.97) 9036.29,4931.96 9036.29,2978.63 9064.96,2978.63 ; 9127.95,1921.26 9102.8,1921.26 ; 9127.95,2944.88 9102.8,2944.88 ; 11023.64,0 11811.02,0 11811.02,6496.06 11023.64,6496.06 ; 8742.51,1921.26 8704.6,1921.26 8704.6,2944.88 8742.51,2944.88 ; 8742.51,1921.26 8816.07,1921.26 ; 8742.51,1921.26 8742.51,2944.88 ; 8742.51,2944.88 8816.07,2944.88 ; 8816.07,1921.26 9102.8,1921.26 ; 8816.07,1921.26 8816.07,2944.88 ; 8816.07,2944.88 9102.8,2944.88 ; 9064.96,2978.63 9064.96,2979.31 9064.96,4923.7 cw(c10393.7,-10639.77) 11722.44,4923.7 11722.44,1218.03 cw(c10393.7,16781.5) 9064.96,1218.03 9064.96,1902.57 9108.34,1902.57 9108.34,1266.97 ccw(c9118.17,1266.97) 9117.36,1257.17 ccw(c10393.7,16781.5) 10299.49,1205.08 ccw(c10299.55,1214.91) 10308.42,1219.16 cw(c10393.7,1259.84) 10478.98,1219.16 ccw(c10487.85,1214.91) 10487.91,1205.08 ccw(c10393.7,16781.5) 11670.04,1257.17 ccw(c11669.23,1266.97) 11679.06,1266.97 11679.06,4874.76 11670.04,4884.56 ccw(c10393.7,-10639.77) 10487.91,4936.65 ccw(c10487.85,4926.82) 10478.98,4922.57 cw(c10393.7,4881.89) 10308.42,4922.57 ccw(c10299.55,4926.82) 10299.49,4936.65 ccw(c10393.7,-10639.77) 9117.36,4884.56 ccw(c9118.17,4874.76) 9108.34,4874.76 9108.34,2979.31 9064.96,2978.63 ; 9102.8,1921.26 9102.8,2944.88 ; 9127.95,1370.08 9127.95,4767.72 11659.45,4767.72 11659.45,1370.08 9127.95,1370.08 ; 9147.64,1381.89 9147.64,4755.91 11639.76,4755.91 11639.76,1381.89 9147.64,1381.89 ; 9259.05,1694.49 11528.35,1694.49 11528.35,4667.72 9259.05,4667.72 9259.05,1694.49 ; 9288.58,1718.11 11498.82,1718.11 11498.82,4632.28 9288.58,4632.28 9288.58,1718.11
